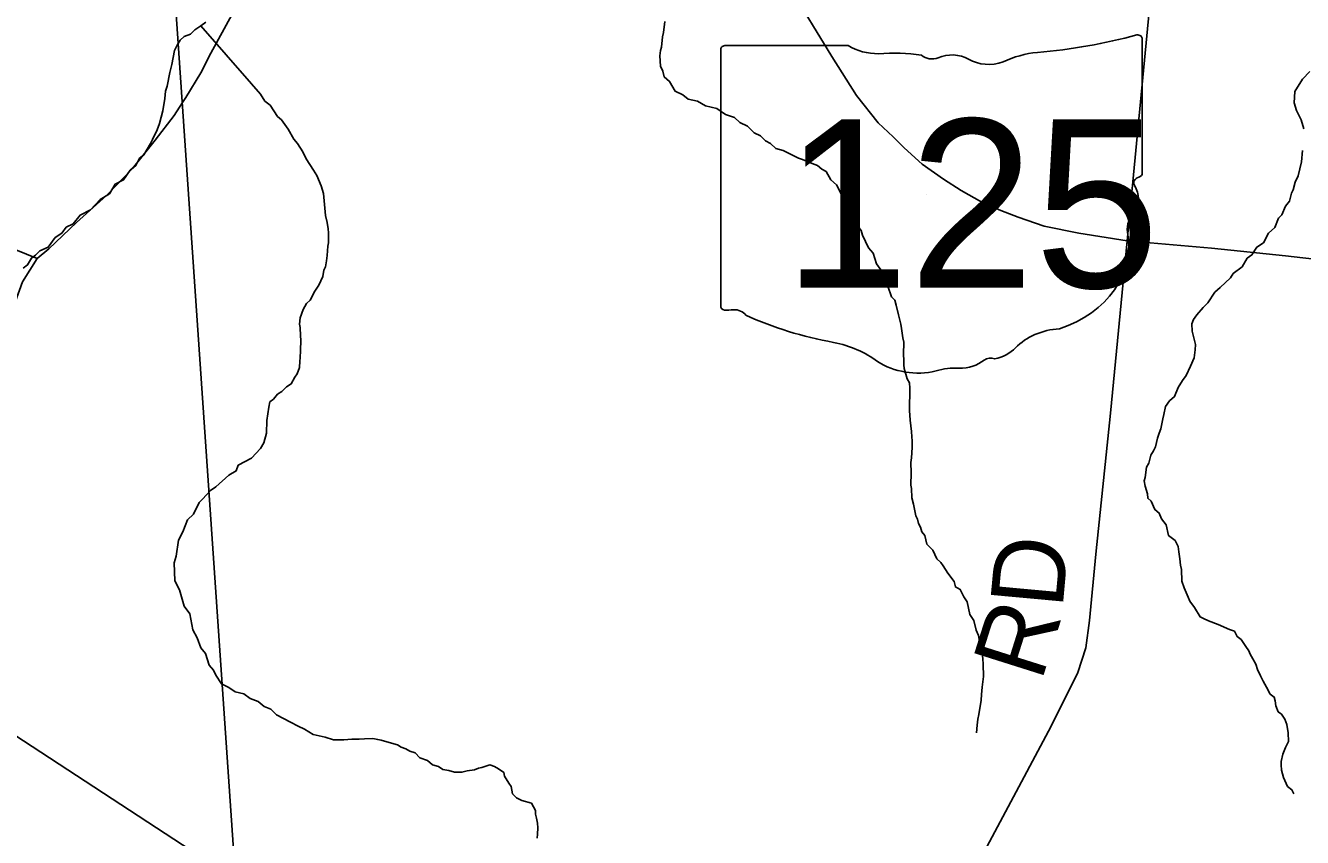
# Model space of a CAD drawing. Extents: x 0 to 39.3, y -3.9 to 22.
# Drawn here: x 7.624 to 8.623, y 15.488 to 16.123 of the extents above; entities that cross this region are included whole.
import ezdxf

# ---------------------------------------------------------------- set-up
doc = ezdxf.new("R2010")
doc.units = 0
for name, color, linetype in [('GM_X_Corporation', 7, 'Continuous'), ('GM_X_County_Road', 7, 'Continuous'), ('GM_X_County_Road_Text', 7, 'Continuous'), ('GM_X_Minor_River', 7, 'Continuous'), ('GM_X_Rail_Line', 7, 'Continuous'), ('GM_X_State_Location', 7, 'Continuous'), ('GM_X_State_Route', 7, 'Continuous'), ('GM_X_State_Shield', 7, 'Continuous'), ('GM_X_Township_Road', 7, 'Continuous')]:
    doc.layers.add(name, color=color, linetype=linetype)

msp = doc.modelspace()

# ---------------------------------------------------------------- linework, layer by layer
at = {"layer": 'GM_X_Corporation'}
msp.add_lwpolyline([(7.89397, 13.9), (8.7, 13.9), (8.7, 17.13724), (7.66327, 17.23426), (7.70243, 16.70782), (7.72454, 16.38622), (7.73835, 16.18516), (7.74674, 16.06315), (7.83678, 14.75308), (7.8533, 14.49864), (7.86853, 14.2638)], close=True, dxfattribs=at)
msp.add_lwpolyline([(7.83678, 14.75308), (7.74674, 16.06315), (7.73835, 16.18516), (7.72454, 16.38622), (7.70243, 16.70782), (7.6579, 16.73471), (7.60466, 16.76574)], dxfattribs=at)
at = {"layer": 'GM_X_County_Road'}
for points in [[(8.48594, 15.95462), (8.51168, 16.22373), (8.51747, 16.26835)], [(7.8619, 14.51368), (7.96418, 14.70383), (8.24577, 15.23587), (8.42637, 15.57488), (8.44732, 15.6168), (8.45364, 15.63609), (8.45631, 15.65738), (8.4613, 15.70927), (8.47293, 15.81971), (8.48594, 15.95462)]]:
    msp.add_lwpolyline(points, dxfattribs=at)
at = {"layer": 'GM_X_Minor_River'}
for points in [[(7.76521, 16.12554), (7.76135, 16.12256), (7.75673, 16.11959), (7.75325, 16.11622), (7.74826, 16.11441), (7.74516, 16.11142), (7.74281, 16.10765), (7.74083, 16.1035), (7.73873, 16.09249), (7.73709, 16.08605), (7.735, 16.07543), (7.73378, 16.07164), (7.7333, 16.06594), (7.7316, 16.05607), (7.72914, 16.04622), (7.72715, 16.0413), (7.72358, 16.03375), (7.72201, 16.03073), (7.71689, 16.02169), (7.71342, 16.01908), (7.71065, 16.01342), (7.70602, 16.00969), (7.70093, 16.00217), (7.6944, 15.99885), (7.69008, 15.99132), (7.68276, 15.98687), (7.675, 15.97863), (7.66694, 15.97458), (7.66148, 15.96783), (7.65611, 15.96525), (7.65259, 15.96037), (7.64758, 15.95703), (7.64212, 15.94951), (7.63559, 15.94658), (7.63211, 15.94321), (7.62902, 15.94098), (7.62588, 15.9357), (7.62241, 15.9331)], [(7.76135, 16.12256), (7.80096, 16.07725), (7.80805, 16.06913), (7.81138, 16.06375), (7.81551, 16.06063), (7.82144, 16.05177), (7.82444, 16.04906), (7.82963, 16.04173), (7.83406, 16.03404), (7.83704, 16.03057), (7.84111, 16.02403), (7.84368, 16.01865), (7.84961, 16.0098), (7.8522, 16.00557), (7.85548, 15.99752), (7.85727, 15.9914), (7.85886, 15.97424), (7.86029, 15.96889), (7.86096, 15.96393), (7.86129, 15.96087), (7.86114, 15.95288), (7.86071, 15.95023), (7.8602, 15.943), (7.85975, 15.93882), (7.8589, 15.93427), (7.85771, 15.93163), (7.85686, 15.92669), (7.85369, 15.9199), (7.85056, 15.915), (7.84701, 15.90821), (7.84392, 15.9056), (7.84155, 15.90069), (7.83915, 15.89426), (7.83867, 15.88932), (7.83901, 15.88665), (7.83927, 15.88018), (7.83959, 15.87674), (7.83944, 15.86875), (7.83896, 15.86305), (7.83891, 15.86039), (7.83844, 15.85545), (7.83683, 15.85053), (7.83488, 15.8479), (7.83212, 15.84261), (7.82827, 15.8404), (7.82478, 15.83665), (7.82131, 15.83443), (7.8182, 15.83067), (7.81549, 15.82843), (7.81466, 15.82426), (7.81295, 15.81401), (7.81277, 15.80412), (7.81073, 15.79654), (7.80798, 15.79202), (7.801, 15.78453), (7.79062, 15.779), (7.78901, 15.77446), (7.78324, 15.77113), (7.77318, 15.76217), (7.76894, 15.7592), (7.76273, 15.75245), (7.76002, 15.74983), (7.75567, 15.74077), (7.75102, 15.73628), (7.74742, 15.72683), (7.74388, 15.72042), (7.74213, 15.70789), (7.74051, 15.70259), (7.74102, 15.6885), (7.7447, 15.68158), (7.74827, 15.66858), (7.75273, 15.66279), (7.75517, 15.65019), (7.75848, 15.64404), (7.76138, 15.636), (7.76511, 15.63175), (7.76799, 15.62256), (7.77135, 15.6187), (7.77318, 15.61486), (7.77762, 15.60793), (7.78328, 15.60517), (7.78817, 15.60166), (7.79499, 15.60002), (7.79988, 15.59651), (7.8063, 15.59412), (7.8108, 15.59023), (7.8161, 15.58824), (7.82058, 15.58359), (7.83152, 15.57808), (7.83755, 15.57493), (7.84246, 15.57256), (7.84923, 15.56825), (7.85871, 15.56619), (7.86515, 15.56418), (7.87314, 15.56404), (7.87962, 15.56469), (7.88533, 15.56459), (7.88952, 15.5649), (7.896, 15.56517), (7.89979, 15.56434), (7.90245, 15.56392)], [(8.12427, 16.12612), (8.12335, 16.11739), (8.12253, 16.11397), (8.12162, 16.106), (8.12081, 16.10335), (8.12036, 16.09917), (8.12097, 16.09116), (8.12281, 16.08733), (8.12386, 16.08274), (8.12799, 16.07924), (8.13242, 16.07155), (8.13846, 16.06879), (8.14258, 16.06529), (8.14978, 16.06364), (8.15619, 16.06011), (8.16491, 16.05805), (8.17168, 16.05337), (8.17887, 16.05096), (8.18298, 16.04708), (8.18902, 16.04432), (8.19426, 16.0389), (8.19916, 16.03653), (8.2029, 16.03266), (8.20705, 16.03068), (8.21117, 16.02681), (8.21685, 16.02519), (8.22892, 16.01927), (8.23194, 16.01808), (8.2395, 16.0149)], [(8.6287, 16.08701), (8.62288, 16.08102), (8.62092, 16.07763), (8.61896, 16.07462), (8.617, 16.07123), (8.61646, 16.06248), (8.61825, 16.05636), (8.62192, 16.04906), (8.62408, 16.04218)], [(8.62301, 16.02506), (8.62209, 16.01633), (8.61961, 16.00533), (8.61724, 16.00042), (8.6156, 15.99436), (8.61441, 15.99172), (8.61278, 15.98565), (8.60966, 15.98152), (8.60687, 15.97472), (8.60416, 15.9721), (8.60137, 15.96491), (8.59634, 15.96043), (8.5924, 15.95289), (8.58739, 15.94955), (8.58347, 15.94353), (8.57962, 15.94093), (8.57569, 15.93414), (8.56874, 15.92893), (8.56678, 15.92554), (8.55865, 15.91807), (8.55439, 15.91433), (8.54891, 15.90605), (8.54542, 15.90231), (8.54037, 15.89668), (8.53764, 15.89292), (8.53643, 15.88952), (8.53671, 15.88381), (8.53919, 15.87349), (8.53911, 15.8693), (8.53823, 15.86284), (8.53545, 15.85642), (8.5319, 15.84925), (8.52916, 15.84511), (8.52564, 15.83984), (8.52284, 15.83266), (8.51898, 15.8293), (8.51585, 15.82478), (8.5146, 15.81872), (8.51377, 15.8153), (8.51211, 15.80734), (8.5109, 15.80393), (8.50969, 15.80015), (8.50805, 15.79332), (8.50647, 15.79031), (8.50451, 15.78691), (8.50287, 15.78047), (8.50091, 15.77746), (8.5, 15.76948), (8.49919, 15.76683)], [(8.2395, 16.0149), (8.24366, 16.01331), (8.24704, 16.01059), (8.25043, 16.00862), (8.25411, 16.00209), (8.25861, 15.99821), (8.26229, 15.99129), (8.26528, 15.98782), (8.2678, 15.98016), (8.27116, 15.97629), (8.27405, 15.96787), (8.27776, 15.96248), (8.27884, 15.95903), (8.28361, 15.94905), (8.28734, 15.9448), (8.28985, 15.93639), (8.29319, 15.93176), (8.29571, 15.92372), (8.29867, 15.91911), (8.30157, 15.91068), (8.30418, 15.90797), (8.30525, 15.90415), (8.30702, 15.8965), (8.30879, 15.88924), (8.30949, 15.8858), (8.3105, 15.87855), (8.3112, 15.87512), (8.31103, 15.8656), (8.31133, 15.86103), (8.31126, 15.85761), (8.31159, 15.85455), (8.31373, 15.84652), (8.31558, 15.84345), (8.31588, 15.83925), (8.31556, 15.82175), (8.31619, 15.81413), (8.31717, 15.80536), (8.31748, 15.80116), (8.3178, 15.79811), (8.31771, 15.79279), (8.31718, 15.7848), (8.31673, 15.781), (8.31697, 15.773), (8.31679, 15.76349), (8.31712, 15.76082), (8.31737, 15.75358), (8.31881, 15.74861), (8.32055, 15.73945), (8.32202, 15.73676), (8.32272, 15.73332), (8.32419, 15.73063), (8.32526, 15.7268), (8.3275, 15.7241), (8.32928, 15.71722), (8.33376, 15.71258), (8.33706, 15.70567), (8.34006, 15.70295), (8.34192, 15.70025), (8.34562, 15.69448), (8.35045, 15.68793), (8.35151, 15.68372), (8.35529, 15.68175), (8.35823, 15.67599), (8.36082, 15.67214), (8.36293, 15.66221), (8.36589, 15.65759), (8.36765, 15.64995), (8.36948, 15.64573), (8.37087, 15.63847), (8.37232, 15.63426), (8.37295, 15.6274), (8.37326, 15.62321), (8.37347, 15.61369), (8.37255, 15.60533), (8.37207, 15.59963), (8.37161, 15.59507), (8.36988, 15.58406), (8.36905, 15.58027), (8.36859, 15.57571), (8.3681, 15.56962)], [(8.49919, 15.76683), (8.49988, 15.76263), (8.50167, 15.75651), (8.50199, 15.75308), (8.50461, 15.75075), (8.50754, 15.74423), (8.51091, 15.74151), (8.51273, 15.73691), (8.51646, 15.73228), (8.51821, 15.72387), (8.52347, 15.71997), (8.52567, 15.71537), (8.52635, 15.71117), (8.52702, 15.70583), (8.52769, 15.70087), (8.52839, 15.69743), (8.5286, 15.68829), (8.53041, 15.68293), (8.5337, 15.67565), (8.53479, 15.67258), (8.53851, 15.66757), (8.54294, 15.66026), (8.54559, 15.65908), (8.54936, 15.65711), (8.55692, 15.65431), (8.56598, 15.65035), (8.56977, 15.64914), (8.57198, 15.64492), (8.57498, 15.64258), (8.57869, 15.63719), (8.58091, 15.63372), (8.582, 15.63104), (8.58422, 15.62758), (8.58643, 15.62335), (8.58788, 15.61914), (8.59007, 15.61416), (8.59228, 15.60993), (8.59486, 15.60532), (8.59781, 15.59994), (8.60081, 15.5976), (8.60152, 15.59455), (8.60221, 15.59073), (8.60403, 15.58613), (8.60666, 15.58418), (8.60926, 15.58033), (8.6107, 15.57612), (8.61173, 15.56963), (8.61198, 15.56277), (8.60962, 15.55825), (8.60762, 15.55295), (8.60637, 15.54726), (8.60633, 15.5446), (8.60663, 15.54041), (8.60805, 15.53467), (8.61135, 15.52776), (8.61473, 15.52504), (8.61619, 15.52197)], [(7.90245, 15.56392), (7.9104, 15.5615), (7.91532, 15.56027), (7.91795, 15.55832), (7.92174, 15.55711), (7.92475, 15.55516), (7.92891, 15.55395), (7.93265, 15.55008), (7.9387, 15.54807), (7.94245, 15.54458), (7.94737, 15.54335), (7.95076, 15.54101), (7.95531, 15.54017), (7.95986, 15.53895), (7.96556, 15.53885), (7.96977, 15.53992), (7.97549, 15.54058), (7.97857, 15.54205), (7.98124, 15.54239), (7.98737, 15.54457), (7.99115, 15.54336), (7.99416, 15.54141), (7.9983, 15.53867), (7.99901, 15.53561), (8.00233, 15.53023), (8.00419, 15.52753), (8.00523, 15.5218), (8.00821, 15.51871), (8.01237, 15.51673), (8.01994, 15.5147), (8.02326, 15.50893), (8.02321, 15.50589), (8.02391, 15.50283), (8.02461, 15.49901), (8.02492, 15.4952), (8.02483, 15.49025), (8.02439, 15.48722)]]:
    msp.add_lwpolyline(points, dxfattribs=at)
at = {"layer": 'GM_X_Rail_Line'}
msp.add_lwpolyline([(5.96967, 16.67439), (6.19906, 16.40813), (6.22179, 16.3901), (6.36667, 16.30308), (6.48929, 16.23894), (7.05826, 15.92412), (7.1182, 15.88999), (7.52529, 15.62712), (8.21224, 15.17774), (8.53336, 14.96683), (8.7, 14.85728)], dxfattribs=at)
at = {"layer": 'GM_X_State_Route'}
for points in [[(8.07381, 16.39756), (8.09032, 16.37156), (8.12793, 16.30965), (8.16461, 16.25032), (8.1917, 16.20198), (8.22178, 16.15321), (8.2548, 16.09881), (8.27418, 16.06819), (8.29117, 16.04668), (8.30299, 16.03576), (8.3115, 16.02725), (8.32563, 16.01439), (8.3423, 16.00261), (8.35607, 15.99391), (8.37219, 15.98485), (8.38705, 15.97834), (8.40064, 15.9729), (8.42092, 15.96601), (8.4481, 15.9604), (8.48594, 15.95462)], [(7.63346, 15.94077), (7.64241, 15.94836), (7.66403, 15.96893), (7.68759, 15.98994), (7.70785, 16.0111), (7.72556, 16.03331), (7.74043, 16.05253), (7.74697, 16.06263), (7.74958, 16.06663), (7.76143, 16.08585), (7.76924, 16.10131), (7.78562, 16.1313), (7.79483, 16.14837), (7.79601, 16.15107)], [(8.48594, 15.95462), (8.55173, 15.9488), (8.6097, 15.94264), (8.66858, 15.93594), (8.7, 15.93271)], [(7.51223, 15.55916), (7.52196, 15.59821), (7.52716, 15.62039), (7.53873, 15.65658), (7.55261, 15.69423), (7.56427, 15.72625), (7.57319, 15.74698), (7.5854, 15.77469), (7.60439, 15.80454), (7.60822, 15.81229), (7.61028, 15.81846), (7.61227, 15.82772), (7.61253, 15.83903), (7.61137, 15.85764), (7.61046, 15.87359), (7.61242, 15.88845), (7.6161, 15.90664), (7.62197, 15.92254), (7.63346, 15.94077)]]:
    msp.add_lwpolyline(points, dxfattribs=at)
at = {"layer": 'GM_X_State_Shield'}
for p, q in [((8.49758, 16.00754), (8.49758, 16.11222)), ((8.168, 16.10382), (8.168, 15.9037)), ((8.26776, 16.10726), (8.17124, 16.10726)), ((8.49755, 16.00756), (8.49758, 16.00754))]:
    msp.add_line(p, q, dxfattribs=at)
for centre, major_axis, start_param, end_param in [((8.38018, 16.3801), (0.34952, 0), 4.814394, 5.042369), ((8.49392, 16.11266), (0.00367, 0), 6.141152, 7.989035), ((8.17177, 16.10425), (0.00382, 0), 1.712693, 3.28349), ((8.29075, 16.1305), (0.03703, 0), 4.042523, 4.731795), ((8.30303, 15.99491), (0.13295, 0), 1.404758, 1.657858), ((8.33321, 16.10528), (0.01068, 0), 3.836095, 5.185415), ((8.34889, 16.08215), (0.02221, 0), 0.950623, 2.079405), ((8.42476, 16.04614), (0.07032, 0), 1.699011, 2.107814), ((8.37756, 16.11388), (0.02672, 0), 4.081561, 5.145723), ((8.49673, 15.99985), (0.00568, 0), 1.883978, 3.671073), ((8.49366, 16.00713), (0.00393, 0), 5.05454, 6.418171), ((8.46061, 15.98662), (0.03409, 0), 5.934695, 6.695948), ((8.51072, 15.96373), (0.0248, 0), 2.387724, 3.262537), ((8.39976, 15.95041), (0.08742, 0), 5.101752, 6.440018), ((8.17181, 15.90326), (0.00385, 0), 3.00124, 4.508301), ((8.17239, 15.92374), (0.0294, 0), 4.665946, 4.897461), ((8.1784, 15.89215), (0.0106, 0), 0.519207, 1.627899), ((8.31223, 16.07195), (0.2524, 0), 4.195997, 4.488961), ((8.43662, 15.84752), (0.04788, 0), 1.647645, 2.488434), ((8.23698, 15.8138), (0.07897, 0), 0.823519, 1.323587), ((8.37595, 15.8843), (0.02824, 0), 4.937069, 5.64225), ((8.32239, 15.89116), (0.05011, 0), 4.026481, 4.996735), ((8.35501, 15.87618), (0.0267, 0), 4.691044, 5.507374), ((8.37916, 15.85679), (0.00752, 0), 1.147584, 2.315152), ((8.35135, 15.82197), (0.04118, 0), 1.495662, 1.94098)]:
    msp.add_ellipse(centre, major_axis=major_axis, ratio=0.8, start_param=start_param, end_param=end_param, dxfattribs=at)
at = {"layer": 'GM_X_Township_Road'}
msp.add_lwpolyline([(7.6166, 15.94736), (7.63346, 15.94077)], dxfattribs=at)

# ---------------------------------------------------------------- texts
at = {"layer": 'GM_X_County_Road_Text'}
for s, rotation, p in [('D', 84.76381, (8.4353, 15.66614)), ('R', 72.46052, (8.41865, 15.60883))]:
    msp.add_text(s, height=0.05682, rotation=rotation, dxfattribs=at).set_placement(p)
at = {"layer": 'GM_X_State_Location'}
for s, p in [('s', (8.32909, 15.99046)), ('r', (8.32908, 15.99046))]:
    msp.add_text(s, height=0.000189, dxfattribs=at).set_placement(p)
msp.add_text('125', height=0.000189, rotation=0.00001, dxfattribs=at).set_placement((8.26222, 15.97668))
at = {"layer": 'GM_X_State_Shield'}
msp.add_text('125', height=0.131836, dxfattribs=at).set_placement((8.21713, 15.91781))

doc.saveas('drawing.dxf')
